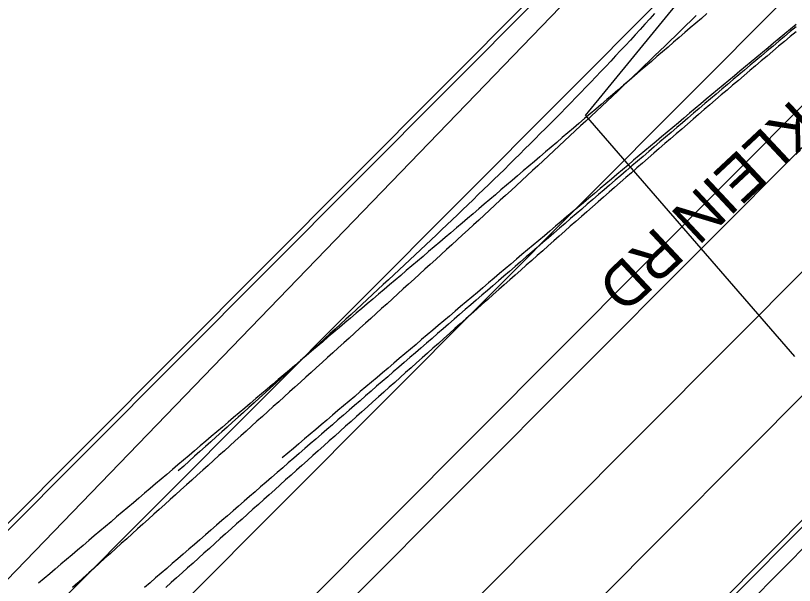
# Model space of a CAD drawing. Extents: x 2252205 to 2259955, y 13788514 to 13798103.
# Drawn here: x 2256171 to 2256277.5, y 13792118.5 to 13792196.5 of the extents above; entities that cross this region are included whole.
import ezdxf

# ---------------------------------------------------------------- set-up
doc = ezdxf.new("R2010")
doc.units = 0
for name, color, linetype in [('D_RDWY_TRACK_BUS', 7, 'Continuous'), ('D_RDWY_TRACK_TRUCK_WB62', 7, 'Continuous'), ('GEOM_CENTERLINE_ALIGN', 7, 'Continuous'), ('Road_EdgeOfPavementOutside', 7, 'Continuous'), ('ROAD_LABEL_ROADWAYS', 7, 'Continuous'), ('ROAD_ROW_EXIST', 7, 'Continuous'), ('ROAD_SCRATCH_PROP_KLEIN_LANES', 7, 'Continuous')]:
    doc.layers.add(name, color=color, linetype=linetype)

msp = doc.modelspace()

# ---------------------------------------------------------------- linework, layer by layer
at = {"layer": 'D_RDWY_TRACK_BUS'}
for points in [[(2256265.59, 13792196.76), (2256264.83, 13792196.1), (2256264.07, 13792195.45), (2256263.31, 13792194.79), (2256262.55, 13792194.14), (2256261.79, 13792193.48), (2256261.03, 13792192.82), (2256260.26, 13792192.17), (2256259.5, 13792191.52), (2256258.74, 13792190.86), (2256257.98, 13792190.21), (2256257.22, 13792189.55), (2256256.46, 13792188.9), (2256255.7, 13792188.25), (2256254.94, 13792187.59), (2256254.17, 13792186.94), (2256253.41, 13792186.29), (2256252.65, 13792185.63), (2256251.89, 13792184.98), (2256251.13, 13792184.33), (2256250.37, 13792183.68), (2256249.6, 13792183.03), (2256248.84, 13792182.37), (2256248.08, 13792181.72), (2256247.32, 13792181.07), (2256246.56, 13792180.42), (2256245.8, 13792179.77), (2256245.04, 13792179.12), (2256244.27, 13792178.47), (2256243.51, 13792177.82), (2256242.75, 13792177.16), (2256241.99, 13792176.51), (2256241.23, 13792175.86), (2256240.47, 13792175.21), (2256239.7, 13792174.56), (2256238.94, 13792173.91), (2256238.18, 13792173.26), (2256237.42, 13792172.61), (2256236.66, 13792171.96), (2256235.9, 13792171.31), (2256235.14, 13792170.66), (2256234.37, 13792170.01), (2256233.61, 13792169.36), (2256232.85, 13792168.71), (2256232.09, 13792168.06), (2256231.33, 13792167.41), (2256230.57, 13792166.76), (2256229.8, 13792166.12), (2256229.04, 13792165.47), (2256228.28, 13792164.82), (2256227.52, 13792164.17), (2256226.76, 13792163.52), (2256226, 13792162.87), (2256225.23, 13792162.22), (2256224.47, 13792161.57), (2256223.71, 13792160.92), (2256222.95, 13792160.27), (2256222.19, 13792159.62), (2256221.43, 13792158.98), (2256220.66, 13792158.33), (2256219.9, 13792157.68), (2256219.14, 13792157.03), (2256218.38, 13792156.38), (2256217.62, 13792155.73), (2256216.85, 13792155.08), (2256216.09, 13792154.43), (2256215.33, 13792153.79), (2256214.57, 13792153.14), (2256213.81, 13792152.49), (2256213.05, 13792151.84), (2256212.28, 13792151.19), (2256211.52, 13792150.54), (2256210.76, 13792149.9), (2256210, 13792149.25), (2256209.24, 13792148.6), (2256208.48, 13792147.95), (2256207.71, 13792147.3), (2256206.95, 13792146.65), (2256206.19, 13792146.01), (2256205.43, 13792145.36), (2256204.67, 13792144.71), (2256203.91, 13792144.06), (2256203.14, 13792143.41), (2256202.38, 13792142.76), (2256201.62, 13792142.12), (2256200.86, 13792141.47), (2256200.1, 13792140.82), (2256199.33, 13792140.17), (2256198.57, 13792139.52), (2256197.81, 13792138.87), (2256197.05, 13792138.23), (2256196.29, 13792137.58), (2256195.53, 13792136.93), (2256194.76, 13792136.28), (2256194, 13792135.63), (2256193.24, 13792134.99), (2256192.48, 13792134.34), (2256191.72, 13792133.69), (2256190.96, 13792133.04), (2256190.19, 13792132.39), (2256189.43, 13792131.75), (2256188.67, 13792131.1), (2256187.91, 13792130.45), (2256187.15, 13792129.8), (2256186.38, 13792129.15), (2256185.62, 13792128.51), (2256184.86, 13792127.86), (2256184.1, 13792127.21), (2256183.34, 13792126.56), (2256182.58, 13792125.91), (2256181.81, 13792125.27), (2256181.05, 13792124.62), (2256180.29, 13792123.97), (2256179.53, 13792123.32), (2256178.77, 13792122.67), (2256178.01, 13792122.03), (2256177.24, 13792121.38), (2256176.48, 13792120.73), (2256175.72, 13792120.08), (2256174.96, 13792119.43), (2256174.2, 13792118.79)], [(2256265.59, 13792196.76), (2256264.83, 13792196.1), (2256264.07, 13792195.45), (2256263.31, 13792194.79), (2256262.55, 13792194.14), (2256261.79, 13792193.48), (2256261.03, 13792192.82), (2256260.26, 13792192.17), (2256259.5, 13792191.52), (2256258.74, 13792190.86), (2256257.98, 13792190.21), (2256257.22, 13792189.55), (2256256.46, 13792188.9), (2256255.7, 13792188.25), (2256254.94, 13792187.59), (2256254.17, 13792186.94), (2256253.41, 13792186.29), (2256252.65, 13792185.63), (2256251.89, 13792184.98), (2256251.13, 13792184.33), (2256250.37, 13792183.68), (2256249.6, 13792183.03), (2256248.84, 13792182.37), (2256248.08, 13792181.72), (2256247.32, 13792181.07), (2256246.56, 13792180.42), (2256245.8, 13792179.77), (2256245.04, 13792179.12), (2256244.27, 13792178.47), (2256243.51, 13792177.82), (2256242.75, 13792177.16), (2256241.99, 13792176.51), (2256241.23, 13792175.86), (2256240.47, 13792175.21), (2256239.7, 13792174.56), (2256238.94, 13792173.91), (2256238.18, 13792173.26), (2256237.42, 13792172.61), (2256236.66, 13792171.96), (2256235.9, 13792171.31), (2256235.14, 13792170.66), (2256234.37, 13792170.01), (2256233.61, 13792169.36), (2256232.85, 13792168.71), (2256232.09, 13792168.06), (2256231.33, 13792167.41), (2256230.57, 13792166.76), (2256229.8, 13792166.12), (2256229.04, 13792165.47), (2256228.28, 13792164.82), (2256227.52, 13792164.17), (2256226.76, 13792163.52), (2256226, 13792162.87), (2256225.23, 13792162.22), (2256224.47, 13792161.57), (2256223.71, 13792160.92), (2256222.95, 13792160.27), (2256222.19, 13792159.62), (2256221.43, 13792158.98), (2256220.66, 13792158.33), (2256219.9, 13792157.68), (2256219.14, 13792157.03), (2256218.38, 13792156.38), (2256217.62, 13792155.73), (2256216.85, 13792155.08), (2256216.09, 13792154.43), (2256215.33, 13792153.79), (2256214.57, 13792153.14), (2256213.81, 13792152.49), (2256213.05, 13792151.84), (2256212.28, 13792151.19), (2256211.52, 13792150.54), (2256210.76, 13792149.9), (2256210, 13792149.25), (2256209.24, 13792148.6), (2256208.48, 13792147.95), (2256207.71, 13792147.3), (2256206.95, 13792146.65), (2256206.19, 13792146.01), (2256205.43, 13792145.36), (2256204.67, 13792144.71), (2256203.91, 13792144.06), (2256203.14, 13792143.41), (2256202.38, 13792142.76), (2256201.62, 13792142.12), (2256200.86, 13792141.47), (2256200.1, 13792140.82), (2256199.33, 13792140.17), (2256198.57, 13792139.52), (2256197.81, 13792138.87), (2256197.05, 13792138.23), (2256196.29, 13792137.58), (2256195.53, 13792136.93), (2256194.76, 13792136.28), (2256194, 13792135.63), (2256193.24, 13792134.99), (2256192.48, 13792134.34), (2256191.72, 13792133.69), (2256190.96, 13792133.04), (2256190.19, 13792132.39), (2256189.43, 13792131.75), (2256188.67, 13792131.1), (2256187.91, 13792130.45), (2256187.15, 13792129.8), (2256186.38, 13792129.15), (2256185.62, 13792128.51), (2256184.86, 13792127.86), (2256184.1, 13792127.21), (2256183.34, 13792126.56), (2256182.58, 13792125.91), (2256181.81, 13792125.27), (2256181.05, 13792124.62), (2256180.29, 13792123.97), (2256179.53, 13792123.32), (2256178.77, 13792122.67), (2256178.01, 13792122.03), (2256177.24, 13792121.38), (2256176.48, 13792120.73), (2256175.72, 13792120.08), (2256174.96, 13792119.43), (2256174.2, 13792118.79)], [(2256264.11, 13792196.49), (2256263.41, 13792195.8), (2256262.7, 13792195.1), (2256261.99, 13792194.41), (2256261.27, 13792193.71), (2256260.56, 13792193.02), (2256259.85, 13792192.33), (2256259.13, 13792191.64), (2256258.42, 13792190.95), (2256257.7, 13792190.26), (2256256.98, 13792189.58), (2256256.26, 13792188.89), (2256255.54, 13792188.2), (2256254.82, 13792187.52), (2256254.1, 13792186.83), (2256253.38, 13792186.15), (2256252.65, 13792185.46), (2256251.93, 13792184.78), (2256251.2, 13792184.09), (2256250.48, 13792183.41), (2256249.75, 13792182.73), (2256249.02, 13792182.05), (2256248.3, 13792181.37), (2256247.57, 13792180.69), (2256246.84, 13792180.01), (2256246.11, 13792179.33), (2256245.38, 13792178.65), (2256244.65, 13792177.97), (2256243.92, 13792177.29), (2256243.19, 13792176.61), (2256242.46, 13792175.93), (2256241.72, 13792175.26), (2256240.99, 13792174.58), (2256240.26, 13792173.9), (2256239.52, 13792173.22), (2256238.79, 13792172.55), (2256238.06, 13792171.87), (2256237.32, 13792171.2), (2256236.59, 13792170.52), (2256235.85, 13792169.85), (2256235.12, 13792169.17), (2256234.38, 13792168.5), (2256233.64, 13792167.82), (2256232.91, 13792167.15), (2256232.17, 13792166.47), (2256231.43, 13792165.8), (2256230.7, 13792165.12), (2256229.96, 13792164.45), (2256229.22, 13792163.78), (2256228.49, 13792163.1), (2256227.75, 13792162.43), (2256227.01, 13792161.76), (2256226.27, 13792161.09), (2256225.53, 13792160.41), (2256224.79, 13792159.74), (2256224.05, 13792159.07), (2256223.31, 13792158.4), (2256222.58, 13792157.72), (2256221.84, 13792157.05), (2256221.1, 13792156.38), (2256220.36, 13792155.71), (2256219.62, 13792155.04), (2256218.88, 13792154.36), (2256218.14, 13792153.69), (2256217.4, 13792153.02), (2256216.66, 13792152.35), (2256215.92, 13792151.68), (2256215.17, 13792151.01), (2256214.43, 13792150.34), (2256213.69, 13792149.67), (2256212.95, 13792149), (2256212.21, 13792148.33), (2256211.47, 13792147.65), (2256210.73, 13792146.98), (2256209.99, 13792146.31), (2256209.25, 13792145.64), (2256208.51, 13792144.97), (2256207.76, 13792144.3), (2256207.02, 13792143.63), (2256206.28, 13792142.96), (2256205.54, 13792142.29), (2256204.8, 13792141.62), (2256204.05, 13792140.95), (2256203.31, 13792140.28), (2256202.57, 13792139.61), (2256201.83, 13792138.94), (2256201.09, 13792138.27), (2256200.34, 13792137.6), (2256199.6, 13792136.93), (2256198.86, 13792136.26), (2256198.12, 13792135.59), (2256197.38, 13792134.92), (2256196.63, 13792134.25), (2256195.89, 13792133.58), (2256195.15, 13792132.91), (2256194.41, 13792132.24), (2256193.66, 13792131.57), (2256192.92, 13792130.91), (2256192.18, 13792130.24), (2256191.44, 13792129.57), (2256190.69, 13792128.9), (2256189.95, 13792128.23), (2256189.21, 13792127.56), (2256188.46, 13792126.89), (2256187.72, 13792126.22), (2256186.98, 13792125.55), (2256186.24, 13792124.88), (2256185.49, 13792124.21), (2256184.75, 13792123.54), (2256184.01, 13792122.87), (2256183.26, 13792122.2), (2256182.52, 13792121.54), (2256181.78, 13792120.87), (2256181.04, 13792120.2), (2256180.29, 13792119.53), (2256179.55, 13792118.86), (2256178.81, 13792118.19)], [(2256277.78, 13792195.25), (2256277.01, 13792194.61), (2256276.24, 13792193.98), (2256275.47, 13792193.34), (2256274.7, 13792192.7), (2256273.94, 13792192.06), (2256273.17, 13792191.43), (2256272.4, 13792190.79), (2256271.63, 13792190.15), (2256270.87, 13792189.51), (2256270.1, 13792188.87), (2256269.33, 13792188.23), (2256268.57, 13792187.59), (2256267.8, 13792186.95), (2256267.04, 13792186.31), (2256266.27, 13792185.66), (2256265.5, 13792185.02), (2256264.74, 13792184.38), (2256263.97, 13792183.74), (2256263.21, 13792183.1), (2256262.44, 13792182.46), (2256261.68, 13792181.81), (2256260.91, 13792181.17), (2256260.15, 13792180.53), (2256259.38, 13792179.88), (2256258.62, 13792179.24), (2256257.86, 13792178.6), (2256257.09, 13792177.95), (2256256.33, 13792177.31), (2256255.56, 13792176.67), (2256254.8, 13792176.02), (2256254.03, 13792175.38), (2256253.27, 13792174.73), (2256252.51, 13792174.09), (2256251.74, 13792173.44), (2256250.98, 13792172.8), (2256250.22, 13792172.15), (2256249.45, 13792171.51), (2256248.69, 13792170.86), (2256247.93, 13792170.22), (2256247.16, 13792169.57), (2256246.4, 13792168.93), (2256245.64, 13792168.28), (2256244.87, 13792167.64), (2256244.11, 13792166.99), (2256243.35, 13792166.35), (2256242.58, 13792165.7), (2256241.82, 13792165.06), (2256241.06, 13792164.41), (2256240.29, 13792163.76), (2256239.53, 13792163.12), (2256238.77, 13792162.47), (2256238.01, 13792161.82), (2256237.24, 13792161.18), (2256236.48, 13792160.53), (2256235.72, 13792159.89), (2256234.95, 13792159.24), (2256234.19, 13792158.59), (2256233.43, 13792157.95), (2256232.67, 13792157.3), (2256231.9, 13792156.65), (2256231.14, 13792156.01), (2256230.38, 13792155.36), (2256229.62, 13792154.71), (2256228.85, 13792154.07), (2256228.09, 13792153.42), (2256227.33, 13792152.77), (2256226.57, 13792152.13), (2256225.81, 13792151.48), (2256225.04, 13792150.83), (2256224.28, 13792150.19), (2256223.52, 13792149.54), (2256222.76, 13792148.89), (2256221.99, 13792148.24), (2256221.23, 13792147.6), (2256220.47, 13792146.95), (2256219.71, 13792146.3), (2256218.95, 13792145.66), (2256218.18, 13792145.01), (2256217.42, 13792144.36), (2256216.66, 13792143.71), (2256215.9, 13792143.07), (2256215.13, 13792142.42), (2256214.37, 13792141.77), (2256213.61, 13792141.12), (2256212.85, 13792140.48), (2256212.09, 13792139.83), (2256211.32, 13792139.18), (2256210.56, 13792138.53), (2256209.8, 13792137.89), (2256209.04, 13792137.24), (2256208.28, 13792136.59), (2256207.51, 13792135.95)], [(2256277.78, 13792195.25), (2256277.01, 13792194.61), (2256276.24, 13792193.98), (2256275.47, 13792193.34), (2256274.7, 13792192.7), (2256273.94, 13792192.06), (2256273.17, 13792191.43), (2256272.4, 13792190.79), (2256271.63, 13792190.15), (2256270.87, 13792189.51), (2256270.1, 13792188.87), (2256269.33, 13792188.23), (2256268.57, 13792187.59), (2256267.8, 13792186.95), (2256267.04, 13792186.31), (2256266.27, 13792185.66), (2256265.5, 13792185.02), (2256264.74, 13792184.38), (2256263.97, 13792183.74), (2256263.21, 13792183.1), (2256262.44, 13792182.46), (2256261.68, 13792181.81), (2256260.91, 13792181.17), (2256260.15, 13792180.53), (2256259.38, 13792179.88), (2256258.62, 13792179.24), (2256257.86, 13792178.6), (2256257.09, 13792177.95), (2256256.33, 13792177.31), (2256255.56, 13792176.67), (2256254.8, 13792176.02), (2256254.03, 13792175.38), (2256253.27, 13792174.73), (2256252.51, 13792174.09), (2256251.74, 13792173.44), (2256250.98, 13792172.8), (2256250.22, 13792172.15), (2256249.45, 13792171.51), (2256248.69, 13792170.86), (2256247.93, 13792170.22), (2256247.16, 13792169.57), (2256246.4, 13792168.93), (2256245.64, 13792168.28), (2256244.87, 13792167.64), (2256244.11, 13792166.99), (2256243.35, 13792166.35), (2256242.58, 13792165.7), (2256241.82, 13792165.06), (2256241.06, 13792164.41), (2256240.29, 13792163.76), (2256239.53, 13792163.12), (2256238.77, 13792162.47), (2256238.01, 13792161.82), (2256237.24, 13792161.18), (2256236.48, 13792160.53), (2256235.72, 13792159.89), (2256234.95, 13792159.24), (2256234.19, 13792158.59), (2256233.43, 13792157.95), (2256232.67, 13792157.3), (2256231.9, 13792156.65), (2256231.14, 13792156.01), (2256230.38, 13792155.36), (2256229.62, 13792154.71), (2256228.85, 13792154.07), (2256228.09, 13792153.42), (2256227.33, 13792152.77), (2256226.57, 13792152.13), (2256225.81, 13792151.48), (2256225.04, 13792150.83), (2256224.28, 13792150.19), (2256223.52, 13792149.54), (2256222.76, 13792148.89), (2256221.99, 13792148.24), (2256221.23, 13792147.6), (2256220.47, 13792146.95), (2256219.71, 13792146.3), (2256218.95, 13792145.66), (2256218.18, 13792145.01), (2256217.42, 13792144.36), (2256216.66, 13792143.71), (2256215.9, 13792143.07), (2256215.13, 13792142.42), (2256214.37, 13792141.77), (2256213.61, 13792141.12), (2256212.85, 13792140.48), (2256212.09, 13792139.83), (2256211.32, 13792139.18), (2256210.56, 13792138.53), (2256209.8, 13792137.89), (2256209.04, 13792137.24), (2256208.28, 13792136.59), (2256207.51, 13792135.95)], [(2256277.78, 13792194.27), (2256276.98, 13792193.6), (2256276.19, 13792192.94), (2256275.39, 13792192.27), (2256274.6, 13792191.6), (2256273.81, 13792190.94), (2256273.02, 13792190.27), (2256272.24, 13792189.61), (2256271.45, 13792188.94), (2256270.67, 13792188.27), (2256269.89, 13792187.61), (2256269.1, 13792186.94), (2256268.33, 13792186.28), (2256267.55, 13792185.61), (2256266.77, 13792184.95), (2256266, 13792184.28), (2256265.22, 13792183.62), (2256264.45, 13792182.95), (2256263.68, 13792182.29), (2256262.91, 13792181.62), (2256262.14, 13792180.95), (2256261.37, 13792180.29), (2256260.6, 13792179.62), (2256259.83, 13792178.96), (2256259.07, 13792178.29), (2256258.3, 13792177.63), (2256257.54, 13792176.96), (2256256.77, 13792176.3), (2256256.01, 13792175.63), (2256255.25, 13792174.96), (2256254.49, 13792174.3), (2256253.72, 13792173.63), (2256252.96, 13792172.97), (2256252.21, 13792172.3), (2256251.45, 13792171.63), (2256250.69, 13792170.97), (2256249.93, 13792170.3), (2256249.17, 13792169.63), (2256248.42, 13792168.97), (2256247.66, 13792168.3), (2256246.9, 13792167.64), (2256246.15, 13792166.97), (2256245.39, 13792166.3), (2256244.64, 13792165.64), (2256243.88, 13792164.97), (2256243.13, 13792164.3), (2256242.38, 13792163.63), (2256241.63, 13792162.97), (2256240.87, 13792162.3), (2256240.12, 13792161.63), (2256239.37, 13792160.97), (2256238.62, 13792160.3), (2256237.87, 13792159.63), (2256237.11, 13792158.97), (2256236.36, 13792158.3), (2256235.61, 13792157.63), (2256234.86, 13792156.96), (2256234.11, 13792156.3), (2256233.36, 13792155.63), (2256232.61, 13792154.96), (2256231.86, 13792154.29), (2256231.12, 13792153.63), (2256230.37, 13792152.96), (2256229.62, 13792152.29), (2256228.87, 13792151.62), (2256228.12, 13792150.95), (2256227.37, 13792150.29), (2256226.63, 13792149.62), (2256225.88, 13792148.95), (2256225.13, 13792148.28), (2256224.38, 13792147.62), (2256223.64, 13792146.95), (2256222.89, 13792146.28), (2256222.14, 13792145.61), (2256221.39, 13792144.94), (2256220.65, 13792144.28), (2256219.9, 13792143.61), (2256219.15, 13792142.94), (2256218.41, 13792142.27), (2256217.66, 13792141.6), (2256216.92, 13792140.93), (2256216.17, 13792140.27), (2256215.42, 13792139.6), (2256214.68, 13792138.93), (2256213.93, 13792138.26), (2256213.19, 13792137.59), (2256212.44, 13792136.93), (2256211.69, 13792136.26), (2256210.95, 13792135.59), (2256210.2, 13792134.92), (2256209.46, 13792134.25), (2256208.71, 13792133.58), (2256207.97, 13792132.92), (2256207.22, 13792132.25), (2256206.48, 13792131.58), (2256205.73, 13792130.91), (2256204.99, 13792130.24), (2256204.24, 13792129.57), (2256203.5, 13792128.91), (2256202.75, 13792128.24), (2256202.01, 13792127.57), (2256201.26, 13792126.9), (2256200.52, 13792126.23), (2256199.77, 13792125.56), (2256199.03, 13792124.89), (2256198.28, 13792124.23), (2256197.54, 13792123.56), (2256196.8, 13792122.89), (2256196.05, 13792122.22), (2256195.31, 13792121.55), (2256194.56, 13792120.88), (2256193.82, 13792120.21), (2256193.07, 13792119.55), (2256192.33, 13792118.88), (2256191.59, 13792118.21)]]:
    msp.add_lwpolyline(points, dxfattribs=at)
at = {"layer": 'D_RDWY_TRACK_TRUCK_WB62'}
for points in [[(2256258.41, 13792196.75), (2256257.76, 13792196.02), (2256257.1, 13792195.3), (2256256.44, 13792194.57), (2256255.78, 13792193.85), (2256255.11, 13792193.12), (2256254.45, 13792192.4), (2256253.78, 13792191.68), (2256253.1, 13792190.96), (2256252.43, 13792190.24), (2256251.76, 13792189.53), (2256251.08, 13792188.81), (2256250.4, 13792188.1), (2256249.72, 13792187.38), (2256249.03, 13792186.67), (2256248.35, 13792185.96), (2256247.66, 13792185.25), (2256246.97, 13792184.54), (2256246.28, 13792183.84), (2256245.59, 13792183.13), (2256244.9, 13792182.43), (2256244.2, 13792181.72), (2256243.5, 13792181.02), (2256242.8, 13792180.32), (2256242.11, 13792179.62), (2256241.4, 13792178.92), (2256240.7, 13792178.22), (2256240, 13792177.52), (2256239.29, 13792176.82), (2256238.59, 13792176.13), (2256237.88, 13792175.43), (2256237.17, 13792174.74), (2256236.46, 13792174.04), (2256235.75, 13792173.35), (2256235.04, 13792172.66), (2256234.32, 13792171.97), (2256233.61, 13792171.28), (2256232.89, 13792170.59), (2256232.18, 13792169.9), (2256231.46, 13792169.21), (2256230.74, 13792168.53), (2256230.02, 13792167.84), (2256229.3, 13792167.16), (2256228.58, 13792166.47), (2256227.86, 13792165.79), (2256227.14, 13792165.1), (2256226.41, 13792164.42), (2256225.69, 13792163.74), (2256224.97, 13792163.06), (2256224.24, 13792162.37), (2256223.51, 13792161.69), (2256222.79, 13792161.01), (2256222.06, 13792160.33), (2256221.33, 13792159.66), (2256220.6, 13792158.98), (2256219.87, 13792158.3), (2256219.14, 13792157.62), (2256218.41, 13792156.95), (2256217.68, 13792156.27), (2256216.95, 13792155.59), (2256216.21, 13792154.92), (2256215.48, 13792154.24), (2256214.75, 13792153.57), (2256214.01, 13792152.9), (2256213.28, 13792152.22), (2256212.54, 13792151.55), (2256211.8, 13792150.88), (2256211.07, 13792150.2), (2256210.33, 13792149.53), (2256209.59, 13792148.86), (2256208.86, 13792148.19), (2256208.12, 13792147.52), (2256207.38, 13792146.85), (2256206.64, 13792146.18), (2256205.9, 13792145.51), (2256205.16, 13792144.84), (2256204.42, 13792144.17), (2256203.68, 13792143.5), (2256202.94, 13792142.83), (2256202.2, 13792142.16), (2256201.46, 13792141.5), (2256200.72, 13792140.83), (2256199.97, 13792140.16), (2256199.23, 13792139.49), (2256198.49, 13792138.83), (2256197.75, 13792138.16), (2256197, 13792137.49), (2256196.26, 13792136.83), (2256195.51, 13792136.16), (2256194.77, 13792135.5), (2256194.03, 13792134.83), (2256193.28, 13792134.17)], [(2256277.77, 13792194.94), (2256276.98, 13792194.28), (2256276.19, 13792193.62), (2256275.4, 13792192.96), (2256274.62, 13792192.31), (2256273.84, 13792191.65), (2256273.06, 13792190.99), (2256272.28, 13792190.33), (2256271.5, 13792189.68), (2256270.72, 13792189.02), (2256269.94, 13792188.36), (2256269.16, 13792187.71), (2256268.39, 13792187.05), (2256267.62, 13792186.39), (2256266.84, 13792185.74), (2256266.07, 13792185.08), (2256265.3, 13792184.43), (2256264.53, 13792183.77), (2256263.76, 13792183.11), (2256262.99, 13792182.46), (2256262.22, 13792181.8), (2256261.45, 13792181.15), (2256260.68, 13792180.49), (2256259.91, 13792179.83), (2256259.15, 13792179.18), (2256258.38, 13792178.52), (2256257.62, 13792177.87), (2256256.85, 13792177.21), (2256256.09, 13792176.56), (2256255.32, 13792175.9), (2256254.56, 13792175.24), (2256253.79, 13792174.59), (2256253.03, 13792173.93), (2256252.27, 13792173.28), (2256251.51, 13792172.62), (2256250.75, 13792171.97), (2256249.98, 13792171.31), (2256249.22, 13792170.65), (2256248.46, 13792170), (2256247.7, 13792169.34), (2256246.94, 13792168.69), (2256246.18, 13792168.03), (2256245.42, 13792167.38), (2256244.66, 13792166.72), (2256243.9, 13792166.06), (2256243.14, 13792165.41), (2256242.38, 13792164.75), (2256241.62, 13792164.1), (2256240.86, 13792163.44), (2256240.11, 13792162.79), (2256239.35, 13792162.13), (2256238.59, 13792161.47), (2256237.83, 13792160.82), (2256237.07, 13792160.16), (2256236.31, 13792159.51), (2256235.56, 13792158.85), (2256234.8, 13792158.2), (2256234.04, 13792157.54), (2256233.28, 13792156.88), (2256232.53, 13792156.23), (2256231.77, 13792155.57), (2256231.01, 13792154.92), (2256230.26, 13792154.26), (2256229.5, 13792153.61), (2256228.74, 13792152.95), (2256227.99, 13792152.29), (2256227.23, 13792151.64), (2256226.47, 13792150.98), (2256225.72, 13792150.33), (2256224.96, 13792149.67), (2256224.2, 13792149.02), (2256223.45, 13792148.36), (2256222.69, 13792147.7), (2256221.93, 13792147.05), (2256221.18, 13792146.39), (2256220.42, 13792145.74), (2256219.67, 13792145.08), (2256218.91, 13792144.43), (2256218.15, 13792143.77), (2256217.4, 13792143.11), (2256216.64, 13792142.46), (2256215.89, 13792141.8), (2256215.13, 13792141.15), (2256214.38, 13792140.49), (2256213.62, 13792139.84), (2256212.86, 13792139.18), (2256212.11, 13792138.52), (2256211.35, 13792137.87), (2256210.6, 13792137.21), (2256209.84, 13792136.56), (2256209.09, 13792135.9), (2256208.33, 13792135.25), (2256207.58, 13792134.59), (2256206.82, 13792133.93), (2256206.06, 13792133.28), (2256205.31, 13792132.62), (2256204.55, 13792131.97), (2256203.8, 13792131.31), (2256203.04, 13792130.66), (2256202.29, 13792130), (2256201.53, 13792129.34), (2256200.78, 13792128.69), (2256200.02, 13792128.03), (2256199.27, 13792127.38), (2256198.51, 13792126.72), (2256197.76, 13792126.06), (2256197, 13792125.41), (2256196.25, 13792124.75), (2256195.49, 13792124.1), (2256194.74, 13792123.44), (2256193.98, 13792122.79), (2256193.23, 13792122.13), (2256192.47, 13792121.47), (2256191.71, 13792120.82), (2256190.96, 13792120.16), (2256190.2, 13792119.51), (2256189.45, 13792118.85), (2256188.69, 13792118.2)]]:
    msp.add_lwpolyline(points, dxfattribs=at)
at = {"layer": 'GEOM_CENTERLINE_ALIGN'}
msp.add_arc((2265119, 13799669.27), 11459.16, 219.418553, 224.327385, dxfattribs=at)
at = {"layer": 'Road_EdgeOfPavementOutside'}
for q in [(2256281.09, 13792222.05), (2256277.55, 13792149.82)]:
    msp.add_line((2256248.97, 13792182.8), q, dxfattribs=at)
at = {"layer": 'ROAD_ROW_EXIST'}
for p, q in [((2256260.79, 13792213.5), (2255831.84, 13791768.87)), ((2256213.9, 13792058.02), (2256315.12, 13792160.36))]:
    msp.add_line(p, q, dxfattribs=at)
at = {"layer": 'ROAD_SCRATCH_PROP_KLEIN_LANES'}
for p, q in [((2256343, 13792300.81), (2256053.56, 13792009.99)), ((2256343.43, 13792300.3), (2256054.04, 13792009.52)), ((2256351.18, 13792291.07), (2256062.54, 13792001.05)), ((2256358.94, 13792281.86), (2256071.05, 13791992.59)), ((2256366.71, 13792272.66), (2256079.56, 13791984.12)), ((2256369.31, 13792269.59), (2256070.61, 13791969.47)), ((2256377.09, 13792260.4), (2256079.12, 13791961)), ((2256384.88, 13792251.22), (2256087.62, 13791952.54)), ((2256392.68, 13792242.04), (2256096.13, 13791944.07)), ((2256393.12, 13792241.53), (2256096.6, 13791943.6))]:
    msp.add_line(p, q, dxfattribs=at)

# ---------------------------------------------------------------- texts
at = {"layer": 'ROAD_LABEL_ROADWAYS'}
msp.add_text('KLEIN RD', height=6, rotation=223.1011, dxfattribs=at).set_placement((2256277.26, 13792185.13))

doc.saveas('drawing.dxf')
